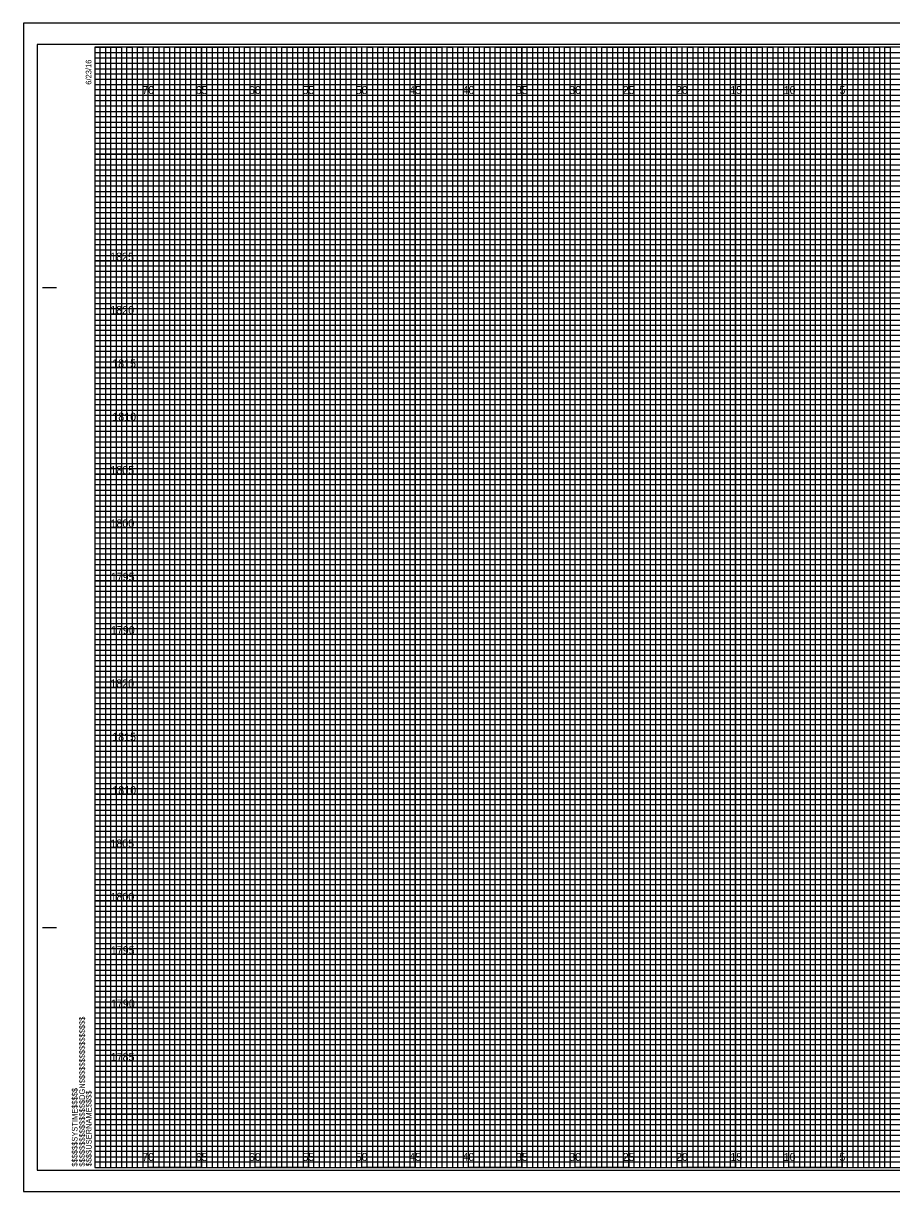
# Model space of a CAD drawing. Extents: x 346 to 514, y -13 to 537.
# Drawn here: x 346 to 427.4, y 317.2 to 426.7 of the extents above; entities that cross this region are included whole.
import ezdxf

# ---------------------------------------------------------------- set-up
doc = ezdxf.new("R2010")
doc.units = 0
for name, color, linetype in [('COGO Default Curve', 7, 'Continuous'), ('Prop Horizontal Alignment', 7, 'Continuous'), ('Prop XS DDE', 7, 'Continuous'), ('Scratch_Level_3', 7, 'Continuous'), ('Sheet Cross Section CELL', 7, 'Continuous'), ('Sheet Cross Section Grid Minor 1 CELL', 7, 'Continuous'), ('Sheet Cross Section Grid Minor 2 CELL', 7, 'Continuous'), ('Sheet Cutting Line CELL', 7, 'Continuous'), ('Sheet DOT Grid CELL', 7, 'Continuous'), ('Sheet Plot Border Inside CELL', 7, 'Continuous'), ('Sheet Plot Border Outside CELL', 7, 'Continuous')]:
    doc.layers.add(name, color=color, linetype=linetype)

msp = doc.modelspace()

# ---------------------------------------------------------------- linework, layer by layer
at = {"layer": 'COGO Default Curve'}
for points in [[(352.75, 424.43), (355.25, 424.43), (355.25, 319.43), (360.25, 319.43), (360.25, 424.43), (365.25, 424.43), (365.25, 319.43), (370.25, 319.43), (370.25, 424.43), (375.25, 424.43), (375.25, 319.43), (380.25, 319.43), (380.25, 424.43), (385.25, 424.43), (385.25, 319.43), (390.25, 319.43), (390.25, 424.43), (395.25, 424.43), (395.25, 319.43), (400.25, 319.43), (400.25, 424.43), (405.25, 424.43), (405.25, 319.43), (410.25, 319.43), (410.25, 424.43), (415.25, 424.43), (415.25, 319.43), (420.25, 319.43), (420.25, 424.43), (425.25, 424.43), (425.25, 319.43), (430.25, 319.43)], [(352.75, 421.93), (490.25, 421.93)], [(352.75, 411.93), (512.75, 411.93), (512.75, 416.93), (352.75, 416.93)], [(352.75, 401.93), (512.75, 401.93), (512.75, 406.93), (352.75, 406.93)], [(352.75, 391.93), (512.75, 391.93), (512.75, 396.93), (352.75, 396.93)], [(352.75, 381.93), (512.75, 381.93), (512.75, 386.93), (352.75, 386.93)], [(352.75, 371.93), (512.75, 371.93), (512.75, 376.93), (352.75, 376.93)], [(352.75, 361.93), (512.75, 361.93), (512.75, 366.93), (352.75, 366.93)], [(352.75, 351.93), (512.75, 351.93), (512.75, 356.93), (352.75, 356.93)], [(352.75, 341.93), (512.75, 341.93), (512.75, 346.93), (352.75, 346.93)], [(352.75, 331.93), (512.75, 331.93), (512.75, 336.93), (352.75, 336.93)], [(352.75, 321.93), (512.75, 321.93), (512.75, 326.93), (352.75, 326.93)]]:
    msp.add_lwpolyline(points, dxfattribs=at)
at = {"layer": 'Prop XS DDE'}
for p, q in [((357.75, 424.43), (352.75, 424.43)), ((357.75, 319.43), (357.75, 424.43)), ((367.75, 424.43), (362.75, 424.43)), ((362.75, 424.43), (362.75, 319.43)), ((367.75, 319.43), (367.75, 424.43)), ((377.75, 424.43), (372.75, 424.43)), ((372.75, 424.43), (372.75, 319.43)), ((377.75, 319.43), (377.75, 424.43)), ((387.75, 424.43), (382.75, 424.43)), ((382.75, 424.43), (382.75, 319.43)), ((387.75, 319.43), (387.75, 424.43)), ((397.75, 424.43), (392.75, 424.43)), ((392.75, 424.43), (392.75, 319.43)), ((397.75, 319.43), (397.75, 424.43)), ((407.75, 424.43), (402.75, 424.43)), ((402.75, 424.43), (402.75, 319.43)), ((407.75, 319.43), (407.75, 424.43)), ((417.75, 424.43), (412.75, 424.43)), ((412.75, 424.43), (412.75, 319.43)), ((417.75, 319.43), (417.75, 424.43)), ((427.75, 424.43), (422.75, 424.43)), ((422.75, 424.43), (422.75, 319.43)), ((362.75, 319.43), (357.75, 319.43)), ((372.75, 319.43), (367.75, 319.43)), ((382.75, 319.43), (377.75, 319.43)), ((392.75, 319.43), (387.75, 319.43)), ((402.75, 319.43), (397.75, 319.43)), ((412.75, 319.43), (407.75, 319.43)), ((422.75, 319.43), (417.75, 319.43))]:
    msp.add_line(p, q, dxfattribs=at)
for points in [[(352.75, 419.43), (512.75, 419.43), (512.75, 414.43), (352.75, 414.43)], [(352.75, 409.43), (512.75, 409.43), (512.75, 404.43), (352.75, 404.43)], [(352.75, 399.43), (512.75, 399.43), (512.75, 394.43), (352.75, 394.43)], [(352.75, 389.43), (512.75, 389.43), (512.75, 384.43), (352.75, 384.43)], [(352.75, 379.43), (512.75, 379.43), (512.75, 374.43), (352.75, 374.43)], [(352.75, 369.43), (512.75, 369.43), (512.75, 364.43), (352.75, 364.43)], [(352.75, 359.43), (512.75, 359.43), (512.75, 354.43), (352.75, 354.43)], [(352.75, 349.43), (512.75, 349.43), (512.75, 344.43), (352.75, 344.43)], [(352.75, 339.43), (512.75, 339.43), (512.75, 334.43), (352.75, 334.43)], [(352.75, 329.43), (512.75, 329.43), (512.75, 324.43), (352.75, 324.43)]]:
    msp.add_lwpolyline(points, dxfattribs=at)
at = {"layer": 'Sheet Cross Section CELL'}
for p, q in [((347.85, 401.93), (349.1, 401.93)), ((347.9, 401.93), (349.15, 401.93)), ((347.85, 341.93), (349.1, 341.93)), ((347.9, 341.93), (349.15, 341.93)), ((352.75, 319.43), (352.75, 319.43)), ((352.75, 319.43), (352.75, 319.43)), ((352.75, 319.43), (352.75, 319.43)), ((352.75, 319.43), (352.75, 319.43)), ((352.75, 319.43), (352.75, 319.43)), ((352.75, 319.43), (352.75, 319.43)), ((352.75, 319.43), (352.75, 319.43))]:
    msp.add_line(p, q, dxfattribs=at)
msp.add_lwpolyline([(512.75, 424.43), (352.75, 424.43), (352.75, 319.43), (512.75, 319.43)], close=True, dxfattribs=at)
at = {"layer": 'Sheet Cross Section Grid Minor 1 CELL'}
for p, q in [((352.75, 423.93), (482.75, 423.93)), ((482.75, 423.42), (352.75, 423.42)), ((352.75, 423.42), (352.75, 422.93)), ((352.75, 422.93), (482.75, 422.93)), ((482.75, 422.37), (352.75, 422.37)), ((352.75, 422.37), (352.75, 421.43)), ((352.75, 421.43), (512.75, 421.43))]:
    msp.add_line(p, q, dxfattribs=at)
for points in [[(352.75, 420.93), (487.75, 420.93), (512.75, 420.93), (512.75, 420.43), (352.75, 420.43)], [(352.75, 419.93), (512.75, 419.93), (512.75, 418.93), (352.75, 418.93)], [(352.75, 418.43), (512.75, 418.43), (512.75, 417.93), (352.75, 417.92)], [(352.75, 417.43), (512.75, 417.43), (512.75, 416.43), (352.75, 416.43)], [(352.75, 415.93), (512.75, 415.93), (512.75, 415.43), (352.75, 415.43)], [(352.75, 414.93), (512.75, 414.93), (512.75, 413.93), (352.75, 413.93)], [(352.75, 413.43), (512.75, 413.43), (512.75, 412.93), (352.75, 412.93)], [(352.75, 412.43), (512.75, 412.43), (512.75, 411.43), (352.75, 411.43)], [(352.75, 410.93), (512.75, 410.93), (512.75, 410.43), (352.75, 410.43)], [(352.75, 409.93), (512.75, 409.93), (512.75, 408.93), (352.75, 408.93)], [(352.75, 408.43), (512.75, 408.43), (512.75, 407.93), (352.75, 407.93)], [(352.75, 407.43), (512.75, 407.43), (512.75, 406.4), (512.75, 405.93), (512.75, 405.43), (352.75, 405.43)], [(352.75, 406.43), (512.75, 406.43), (512.75, 405.93), (352.75, 405.93)], [(352.75, 404.93), (512.75, 404.93), (512.75, 403.93), (352.75, 403.94)], [(352.75, 403.94), (512.75, 403.93), (512.75, 403.43), (352.75, 403.43)], [(352.75, 402.93), (512.75, 402.93), (512.75, 402.43), (352.75, 402.43)], [(352.75, 401.43), (512.75, 401.43), (512.75, 400.93), (352.75, 400.93)], [(352.75, 400.43), (512.75, 400.43), (512.75, 399.93), (352.75, 399.93)], [(352.71, 398.87), (512.75, 398.87), (512.75, 398.37), (352.71, 398.37)], [(352.75, 397.93), (512.75, 397.93), (512.75, 397.43), (352.75, 397.43)], [(352.75, 396.43), (512.75, 396.43), (512.75, 395.93), (352.75, 395.93)], [(352.75, 395.43), (512.75, 395.43), (512.75, 394.93), (352.75, 394.93)], [(352.75, 393.93), (512.75, 393.93), (512.75, 393.43), (352.75, 393.43)], [(352.75, 392.93), (512.75, 392.93), (512.75, 392.43), (352.75, 392.43)], [(352.75, 391.43), (512.75, 391.43), (512.75, 390.93), (352.75, 390.93)], [(352.75, 390.43), (512.75, 390.43), (512.75, 389.93), (352.75, 389.93)], [(352.75, 388.93), (512.75, 388.93), (512.74, 388.42), (352.75, 388.43)], [(352.75, 387.93), (512.75, 387.93), (512.75, 387.43), (352.75, 387.43)], [(352.75, 386.43), (512.75, 386.43), (512.75, 385.93), (352.75, 385.93)], [(352.75, 385.43), (512.75, 385.43), (512.75, 384.93), (352.75, 384.93)], [(352.75, 383.93), (512.75, 383.93), (512.75, 383.43), (352.75, 383.43)], [(352.75, 382.93), (512.75, 382.93), (512.75, 382.43), (352.75, 382.43)], [(352.75, 381.43), (512.75, 381.43), (512.75, 380.93), (352.75, 380.93)], [(352.75, 380.43), (512.75, 380.43), (512.75, 379.93), (352.75, 379.93)], [(352.75, 378.93), (512.75, 378.93), (512.75, 378.43), (352.75, 378.43)], [(352.75, 377.92), (512.78, 377.88), (512.75, 377.43), (352.75, 377.43)], [(352.75, 376.43), (512.75, 376.43), (512.75, 375.93), (352.75, 375.93)], [(352.75, 375.43), (512.75, 375.43), (512.75, 374.93), (352.75, 374.93)], [(352.75, 373.93), (512.75, 373.93), (512.75, 373.43), (352.75, 373.43)], [(352.75, 372.93), (512.75, 372.93), (512.75, 372.43), (352.75, 372.43)], [(352.75, 371.43), (512.75, 371.43), (512.75, 370.93), (352.75, 370.93)], [(352.75, 370.43), (512.75, 370.43), (512.75, 369.93), (352.75, 369.93)], [(352.75, 368.93), (512.75, 368.93), (512.75, 368.43), (352.75, 368.43)], [(352.75, 367.93), (512.75, 367.93), (512.75, 367.43), (352.75, 367.43)], [(352.75, 366.43), (512.75, 366.43), (512.75, 365.93), (352.75, 365.93)], [(352.75, 365.43), (512.75, 365.43), (512.75, 364.93), (352.75, 364.93)], [(352.75, 363.93), (512.75, 363.93), (512.75, 363.43), (352.75, 363.43)], [(352.75, 362.93), (512.75, 362.93), (512.75, 362.43), (352.75, 362.43)], [(352.75, 361.43), (512.75, 361.43), (512.75, 360.93), (352.75, 360.93)], [(352.75, 360.43), (512.75, 360.43), (512.75, 359.93), (352.75, 359.93)], [(352.75, 358.93), (512.75, 358.93), (512.74, 358.42), (352.75, 358.43)], [(352.75, 357.93), (512.75, 357.93), (512.75, 357.43), (352.75, 357.43)], [(352.75, 356.43), (512.75, 356.43), (512.75, 355.93), (352.75, 355.93)], [(352.75, 355.43), (512.75, 355.43), (512.75, 354.93), (352.75, 354.93)], [(352.75, 353.93), (512.75, 353.93), (512.75, 353.43), (352.75, 353.43)], [(352.75, 352.93), (512.75, 352.93), (512.75, 352.43), (352.75, 352.43)], [(352.75, 351.43), (512.75, 351.43), (512.75, 350.93), (352.75, 350.93)], [(352.75, 350.43), (512.75, 350.43), (512.75, 349.93), (352.75, 349.93)], [(352.75, 348.93), (512.75, 348.93), (512.75, 348.43), (352.75, 348.43)], [(352.75, 347.92), (512.78, 347.88), (512.75, 347.43), (352.75, 347.43)], [(352.75, 346.43), (512.75, 346.43), (512.75, 345.93), (352.75, 345.93)], [(352.75, 345.43), (512.75, 345.43), (512.75, 344.93), (352.75, 344.93)], [(352.75, 343.93), (512.75, 343.93), (512.75, 343.43), (352.75, 343.43)], [(352.75, 342.93), (512.75, 342.93), (512.75, 342.43), (352.75, 342.43)], [(352.75, 341.43), (512.75, 341.43), (512.75, 340.93), (352.75, 340.93)], [(352.75, 340.43), (512.75, 340.43), (512.75, 339.93), (352.75, 339.93)], [(352.75, 338.93), (512.75, 338.93), (512.75, 338.43), (352.75, 338.43)], [(352.75, 337.93), (512.75, 337.93), (512.75, 337.43), (352.75, 337.43)], [(352.75, 336.43), (512.75, 336.43), (512.75, 335.93), (352.75, 335.93)], [(352.75, 335.43), (512.75, 335.43), (512.75, 334.93), (352.75, 334.93)], [(352.75, 333.93), (512.75, 333.93), (512.75, 333.43), (352.75, 333.43)], [(352.75, 332.93), (512.75, 332.93), (512.75, 332.43), (352.75, 332.43)], [(352.75, 331.43), (512.75, 331.43), (512.75, 330.93), (352.75, 330.93)], [(352.75, 330.43), (512.75, 330.43), (512.75, 329.93), (352.75, 329.93)], [(352.75, 328.93), (512.75, 328.93), (512.75, 328.43), (352.75, 328.43)], [(352.75, 327.93), (512.75, 327.93), (512.75, 327.43), (352.75, 327.43)], [(352.75, 326.43), (512.75, 326.43), (512.75, 325.93), (352.75, 325.93)], [(352.75, 325.43), (512.75, 325.43), (512.75, 324.93), (352.75, 324.93)], [(352.75, 323.93), (512.75, 323.93), (512.75, 323.43), (352.75, 323.43)], [(352.75, 322.93), (512.75, 322.93), (512.75, 322.43), (352.75, 322.43)], [(352.75, 321.43), (512.75, 321.43), (512.75, 320.93), (352.75, 320.93)], [(352.75, 320.43), (512.75, 320.43), (512.75, 319.93), (352.75, 319.93)]]:
    msp.add_lwpolyline(points, dxfattribs=at)
at = {"layer": 'Sheet Cross Section Grid Minor 2 CELL'}
for points in [[(352.75, 319.43), (353.25, 319.43), (353.25, 424.43), (353.75, 424.43), (353.75, 319.43)], [(353.75, 319.43), (354.25, 319.43), (354.25, 424.43), (354.75, 424.43), (354.75, 319.43)], [(355.25, 319.43), (355.75, 319.43), (355.75, 424.43), (356.25, 424.43), (356.25, 319.43)], [(356.25, 319.43), (356.75, 319.43), (356.75, 424.43), (357.25, 424.43), (357.25, 319.43)], [(357.75, 319.43), (358.25, 319.43), (358.25, 424.43), (358.75, 424.43), (358.75, 319.43)], [(358.75, 319.43), (359.25, 319.43), (359.25, 424.43), (359.75, 424.43), (359.75, 319.43)], [(360.25, 319.43), (360.75, 319.43), (360.75, 424.43), (361.25, 424.43), (361.25, 319.43)], [(361.25, 319.43), (361.75, 319.43), (361.75, 424.43), (362.25, 424.43), (362.25, 319.43)], [(362.75, 319.43), (363.25, 319.43), (363.25, 424.43), (363.75, 424.43), (363.75, 319.43)], [(363.75, 319.43), (364.25, 319.43), (364.25, 424.43), (364.75, 424.43), (364.75, 319.43)], [(365.25, 319.43), (365.75, 319.43), (365.75, 424.43), (366.25, 424.43), (366.25, 319.43)], [(366.25, 319.43), (366.75, 319.43), (366.75, 424.43), (367.25, 424.43), (367.25, 319.43)], [(367.75, 319.43), (368.25, 319.43), (368.25, 424.43), (368.75, 424.43), (368.75, 319.43)], [(368.75, 319.43), (369.25, 319.43), (369.25, 424.43), (369.75, 424.43), (369.75, 319.43)], [(370.25, 319.43), (370.75, 319.43), (370.75, 424.43), (371.25, 424.43), (371.25, 319.43)], [(371.25, 319.43), (371.75, 319.43), (371.75, 424.43), (372.25, 424.43), (372.25, 319.43)], [(372.75, 319.43), (373.25, 319.43), (373.25, 424.43), (373.75, 424.43), (373.75, 319.43)], [(373.75, 319.43), (374.25, 319.43), (374.25, 424.43), (374.75, 424.43), (374.75, 319.43)], [(375.25, 319.43), (375.75, 319.43), (375.75, 424.43), (376.25, 424.43), (376.25, 319.43)], [(376.25, 319.43), (376.75, 319.43), (376.75, 424.43), (377.25, 424.43), (377.25, 319.43)], [(377.75, 319.43), (378.25, 319.43), (378.25, 424.43), (378.75, 424.43), (378.75, 319.43)], [(378.75, 319.43), (379.25, 319.43), (379.25, 424.43), (379.75, 424.43), (379.75, 319.43)], [(380.25, 319.43), (380.75, 319.43), (380.75, 424.43), (381.25, 424.43), (381.25, 319.43)], [(381.25, 319.43), (381.75, 319.43), (381.75, 424.43), (382.25, 424.43), (382.25, 319.43)], [(382.75, 319.43), (383.25, 319.43), (383.25, 424.43), (383.75, 424.43), (383.75, 319.43)], [(383.75, 319.43), (384.25, 319.43), (384.25, 424.43), (384.75, 424.43), (384.75, 319.43)], [(385.25, 319.43), (385.75, 319.43), (385.75, 424.43), (386.25, 424.43), (386.25, 319.43)], [(386.25, 319.43), (386.75, 319.43), (386.75, 424.43), (387.25, 424.43), (387.25, 319.43)], [(387.75, 319.43), (388.25, 319.43), (388.25, 424.43), (388.75, 424.43), (388.75, 319.43)], [(388.75, 319.43), (389.25, 319.43), (389.25, 424.43), (389.75, 424.43), (389.75, 319.43)], [(390.25, 319.43), (390.75, 319.43), (390.75, 424.43), (391.25, 424.43), (391.25, 319.43)], [(391.25, 319.43), (391.75, 319.43), (391.75, 424.43), (392.25, 424.43), (392.25, 319.43)], [(392.75, 319.43), (393.25, 319.43), (393.25, 424.43), (393.75, 424.43), (393.75, 319.43)], [(393.75, 319.43), (394.25, 319.43), (394.25, 424.43), (394.75, 424.43), (394.75, 319.43)], [(395.25, 319.43), (395.75, 319.43), (395.75, 424.43), (396.25, 424.43), (396.25, 319.43)], [(396.25, 319.43), (396.75, 319.43), (396.75, 424.43), (397.25, 424.43), (397.25, 319.43)], [(397.75, 319.43), (398.25, 319.43), (398.25, 424.43), (398.75, 424.43), (398.75, 319.43)], [(398.75, 319.43), (399.25, 319.43), (399.25, 424.43), (399.75, 424.43), (399.75, 319.43)], [(400.25, 319.43), (400.75, 319.43), (400.75, 424.43), (401.25, 424.43), (401.25, 319.43)], [(401.25, 319.43), (401.75, 319.43), (401.75, 424.43), (402.25, 424.43), (402.25, 319.43)], [(402.75, 319.43), (403.25, 319.43), (403.25, 424.43), (403.75, 424.43), (403.75, 319.43)], [(403.75, 319.43), (404.25, 319.43), (404.25, 424.43), (404.75, 424.43), (404.75, 319.43)], [(405.25, 319.43), (405.75, 319.43), (405.75, 424.43), (406.25, 424.43), (406.25, 319.43)], [(406.25, 319.43), (406.75, 319.43), (406.75, 424.43), (407.25, 424.43), (407.25, 319.43)], [(407.75, 319.43), (408.25, 319.43), (408.25, 424.43), (408.75, 424.43), (408.75, 319.43)], [(408.75, 319.43), (409.25, 319.43), (409.25, 424.43), (409.75, 424.43), (409.75, 319.43)], [(410.25, 319.43), (410.75, 319.43), (410.75, 424.43), (411.25, 424.43), (411.25, 319.43)], [(411.25, 319.43), (411.75, 319.43), (411.75, 424.43), (412.25, 424.43), (412.25, 319.43)], [(412.75, 319.43), (413.25, 319.43), (413.25, 424.43), (413.75, 424.43), (413.75, 319.43)], [(413.75, 319.43), (414.25, 319.43), (414.25, 424.43), (414.75, 424.43), (414.75, 319.43)], [(415.25, 319.43), (415.75, 319.43), (415.75, 424.43), (416.25, 424.43), (416.25, 319.43)], [(416.25, 319.43), (416.75, 319.43), (416.75, 424.43), (417.25, 424.43), (417.25, 319.43)], [(417.75, 319.43), (418.25, 319.43), (418.25, 424.43), (418.75, 424.43), (418.75, 319.43)], [(418.75, 319.43), (419.25, 319.43), (419.25, 424.43), (419.75, 424.43), (419.75, 319.43)], [(420.25, 319.43), (420.75, 319.43), (420.75, 424.43), (421.25, 424.43), (421.25, 319.43)], [(421.25, 319.43), (421.75, 319.43), (421.75, 424.43), (422.25, 424.43), (422.25, 319.43)], [(422.75, 319.43), (423.25, 319.43), (423.25, 424.43), (423.75, 424.43), (423.75, 319.43)], [(423.75, 319.43), (424.25, 319.43), (424.25, 424.43), (424.75, 424.43), (424.75, 319.43)], [(425.25, 319.43), (425.75, 319.43), (425.75, 424.43), (426.25, 424.43), (426.25, 319.43)], [(426.25, 319.43), (426.75, 319.43), (426.75, 424.43), (427.25, 424.43), (427.25, 319.43)]]:
    msp.add_lwpolyline(points, dxfattribs=at)
at = {"layer": 'Sheet Cutting Line CELL'}
for p, q in [((514.4, 426.68), (346.05, 426.68)), ((346.05, 426.68), (346.05, 317.18)), ((346.05, 317.18), (514.4, 317.18))]:
    msp.add_line(p, q, dxfattribs=at)
at = {"layer": 'Sheet DOT Grid CELL'}
for p, q in [((357.75, 319.43), (357.75, 424.43)), ((362.75, 319.43), (362.75, 424.43)), ((367.75, 319.43), (367.75, 424.43)), ((372.75, 319.43), (372.75, 424.43)), ((377.75, 319.43), (377.75, 424.43)), ((382.75, 319.43), (382.75, 424.43)), ((387.75, 319.43), (387.75, 424.43)), ((392.75, 319.43), (392.75, 424.43)), ((397.75, 319.43), (397.75, 424.43)), ((402.75, 319.43), (402.75, 424.43)), ((407.75, 319.43), (407.75, 424.43)), ((412.75, 319.43), (412.75, 424.43)), ((417.75, 319.43), (417.75, 424.43)), ((422.75, 319.43), (422.75, 424.43)), ((352.75, 419.43), (512.75, 419.43)), ((352.75, 414.43), (512.75, 414.43)), ((352.75, 409.43), (512.75, 409.43)), ((352.75, 404.43), (512.75, 404.43)), ((352.75, 399.43), (512.75, 399.43)), ((352.75, 394.43), (512.75, 394.43)), ((352.75, 389.43), (512.75, 389.43)), ((352.75, 384.43), (512.75, 384.43)), ((352.75, 379.43), (512.75, 379.43)), ((352.75, 374.43), (512.75, 374.43)), ((352.75, 369.43), (512.75, 369.43)), ((352.75, 364.43), (512.75, 364.43)), ((352.75, 359.43), (512.75, 359.43)), ((352.75, 354.43), (512.75, 354.43)), ((352.75, 349.43), (512.75, 349.43)), ((352.75, 344.43), (512.75, 344.43)), ((352.75, 339.43), (512.75, 339.43)), ((352.75, 334.43), (512.75, 334.43)), ((352.75, 329.43), (512.75, 329.43)), ((352.75, 324.43), (512.75, 324.43))]:
    msp.add_line(p, q, dxfattribs=at)
at = {"layer": 'Sheet Plot Border Inside CELL'}
msp.add_lwpolyline([(347.35, 319.18), (513.95, 319.18), (513.95, 424.68), (347.35, 424.68)], close=True, dxfattribs=at)
at = {"layer": 'Sheet Plot Border Outside CELL'}
msp.add_lwpolyline([(346.05, 317.18), (514.4, 317.18), (514.4, 426.68), (346.05, 426.68)], close=True, dxfattribs=at)

# ---------------------------------------------------------------- texts
at = {"layer": 'Prop Horizontal Alignment'}
for s, p in [('1825', (354.18, 404.43)), ('1820', (354.19, 399.43)), ('1815', (354.37, 394.43)), ('1810', (354.38, 389.43)), ('1805', (354.2, 384.43)), ('1800', (354.21, 379.43)), ('1795', (354.24, 374.43)), ('1790', (354.25, 369.43)), ('1820', (354.19, 364.43)), ('1815', (354.37, 359.43)), ('1810', (354.38, 354.43)), ('1805', (354.2, 349.43)), ('1800', (354.21, 344.43)), ('1795', (354.24, 339.43)), ('1790', (354.25, 334.43)), ('1785', (354.23, 329.43))]:
    msp.add_text(s, height=0.75, dxfattribs=at).set_placement(p)
at = {"layer": 'Scratch_Level_3'}
for s, p in [('70', (357.18, 420.05)), ('65', (362.19, 420.05)), ('60', (367.18, 420.05)), ('55', (372.19, 420.05)), ('50', (377.18, 420.05)), ('45', (382.19, 420.05)), ('40', (387.18, 420.05)), ('35', (392.19, 420.05)), ('30', (397.18, 420.05)), ('25', (402.19, 420.05)), ('20', (407.18, 420.05)), ('15', (412.28, 420.05)), ('10', (417.27, 420.05)), ('5', (422.49, 420.05)), ('70', (357.18, 320.05)), ('65', (362.19, 320.05)), ('60', (367.18, 320.05)), ('55', (372.19, 320.05)), ('50', (377.18, 320.05)), ('45', (382.19, 320.05)), ('40', (387.18, 320.05)), ('35', (392.19, 320.05)), ('30', (397.18, 320.05)), ('25', (402.19, 320.05)), ('20', (407.18, 320.05)), ('15', (412.28, 320.05)), ('10', (417.27, 320.05)), ('5', (422.49, 320.05))]:
    msp.add_text(s, height=0.75, dxfattribs=at).set_placement(p)
at = {"layer": 'Sheet Cross Section CELL'}
for s, p in [('6/23/16', (352.42, 420.93)), ('$$$$$$$$$$$$$$$$DGN$$$$$$$$$$$$$$$$', (351.81, 319.52)), ('$$$$$$SYSTIME$$$$$', (351.12, 319.52)), ('$$$$USERNAME$$$$', (352.44, 319.54))]:
    msp.add_text(s, height=0.525, rotation=90, dxfattribs=at).set_placement(p)

doc.saveas('drawing.dxf')
